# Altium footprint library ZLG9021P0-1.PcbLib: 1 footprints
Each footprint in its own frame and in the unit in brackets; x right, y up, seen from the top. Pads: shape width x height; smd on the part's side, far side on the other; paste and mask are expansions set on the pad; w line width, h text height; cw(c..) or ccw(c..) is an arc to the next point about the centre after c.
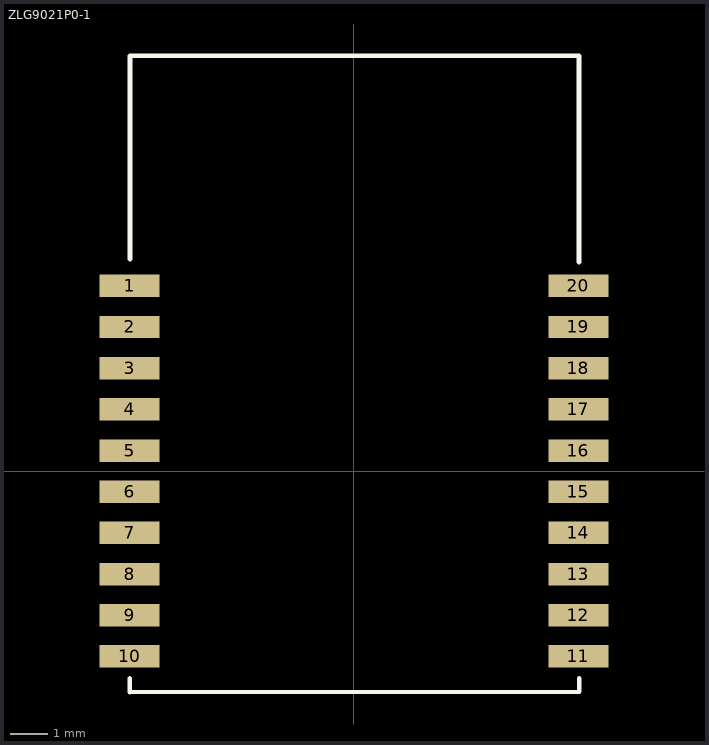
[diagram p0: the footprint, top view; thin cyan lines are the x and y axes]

## ZLG9021P0-1 [mm]
pads (20):
  rect 1.6x0.6 smd: 1(-5.994,4.95) 2(-5.994,3.85) 3(-5.994,2.75) 4(-5.994,1.65) 5(-5.994,0.55) 6(-5.994,-0.55) 7(-5.994,-1.65) 8(-5.994,-2.75) 9(-5.994,-3.85) 10(-5.994,-4.95) 11(5.994,-4.95) 12(5.994,-3.85) 13(5.994,-2.75) 14(5.994,-1.65) 15(5.994,-0.55) 16(5.994,0.55) 17(5.994,1.65) 18(5.994,2.75) 19(5.994,3.85) 20(5.994,4.95)
Top Overlay:
  lines w0.127: -5.994,-5.54 -5.994,-5.906 6.021,-5.896 6.021,-5.53 ; -5.987,5.661 -5.987,11.094 6.013,11.094 6.013,5.585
